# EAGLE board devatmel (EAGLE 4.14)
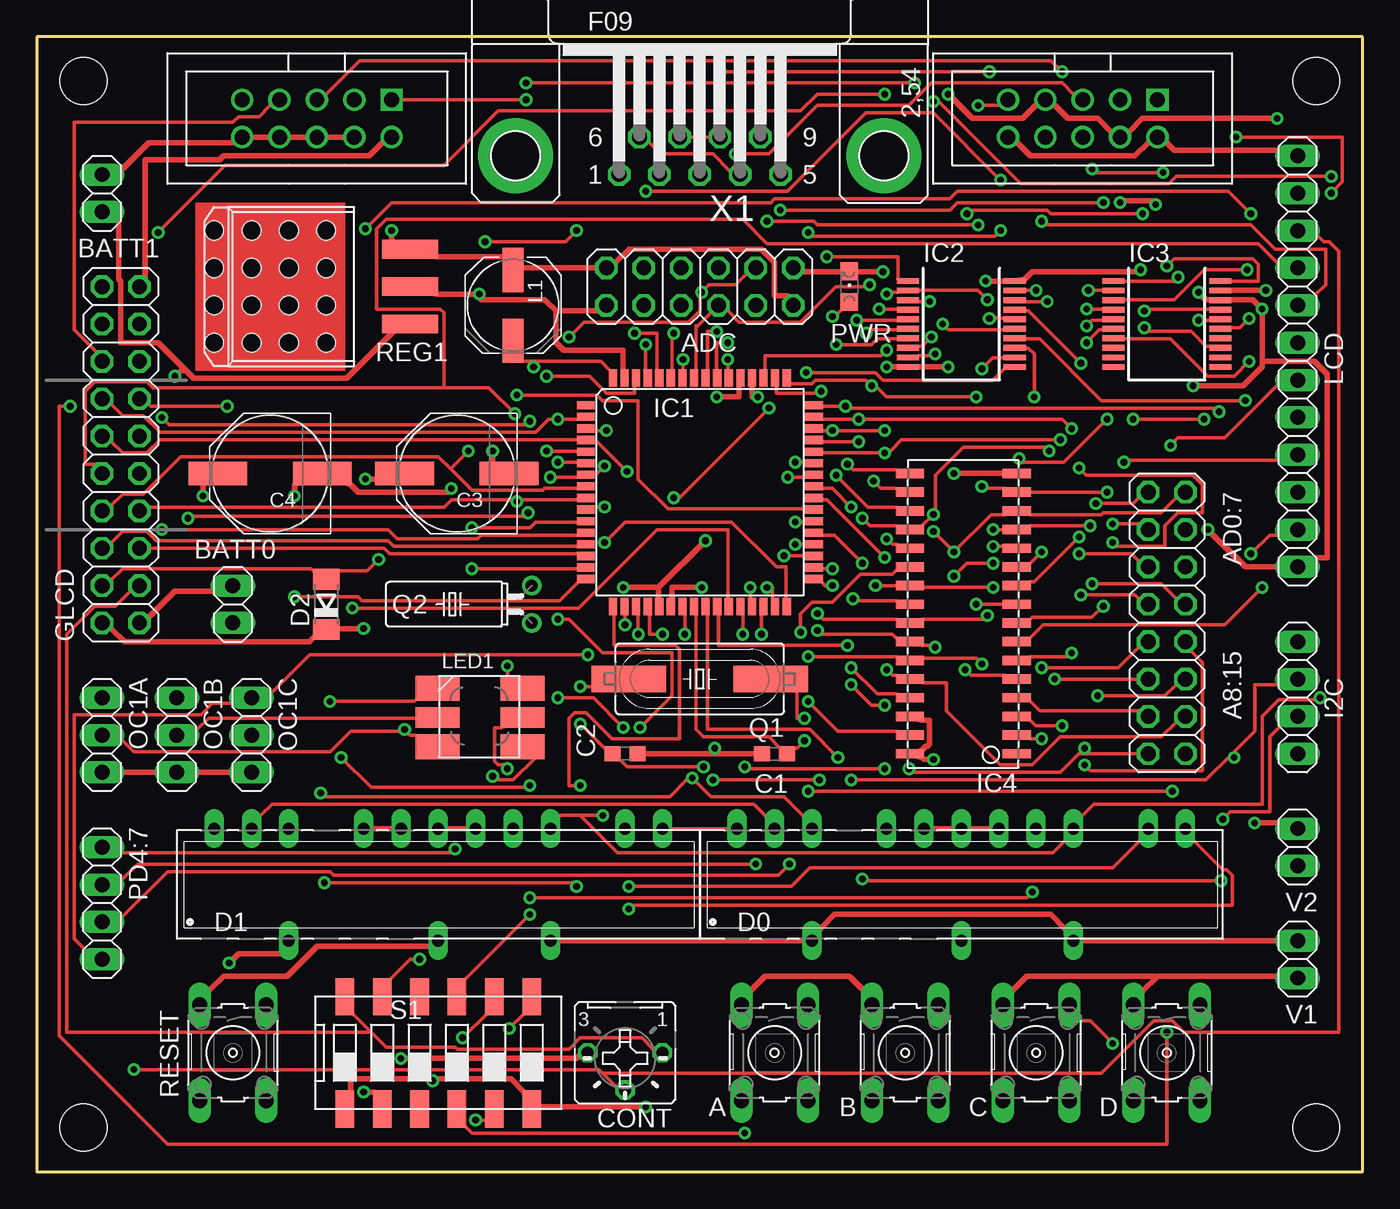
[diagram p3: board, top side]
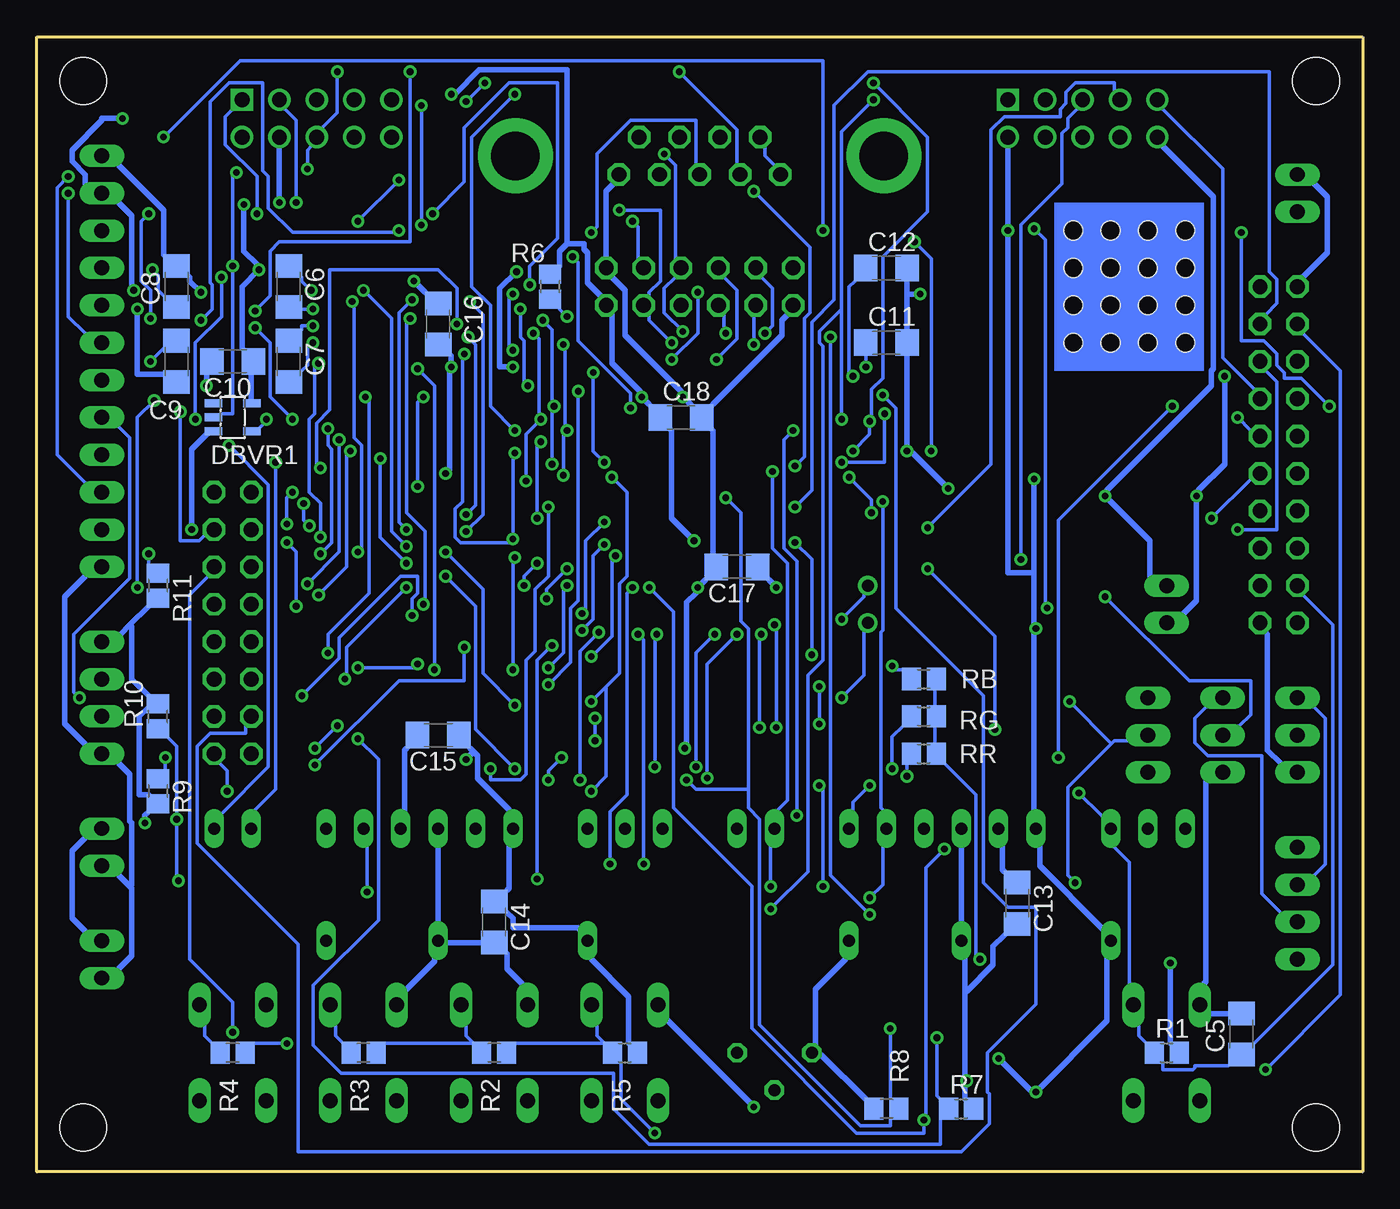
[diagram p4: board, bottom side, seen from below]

Size 90.15 x 77.14 mm. Coordinates in mm from the lower left corner, seen from the top.
Outline: 0,0 90.15,0 90.15,77.14 0,77.14 0,0
Copper layers (1*16): Top 0.035mm / dielectric 1.5mm / Bottom 0.035mm
Design rules "default": minimum track width 10mil, minimum drill 18mil, track to track 8mil, track to pad 8mil, pad to pad 8mil, via to via 8mil, smd to smd 8mil, copper to edge 40mil, drill to drill 8mil, minimum pad ring 10mil, minimum via ring 8mil, stop-mask expansion 4mil, vias tented up to drill 0mil, thermal gap 10mil
Net classes: 1 signal: width 0.254 mm; 2 power: width 0.381 mm
Holes 3.17 mm at 3.17,74.13 86.99,74.13 3.17,3.01 86.99,3.01

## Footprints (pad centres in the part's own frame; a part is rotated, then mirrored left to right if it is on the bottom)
B3F-10XX = drill 1.016 long: 1 -3.251,2.261; 2 3.251,2.261; 3 -3.251,-2.261; 4 3.251,-2.261
2X04 = drill 1.016 octagon: 1 -3.81,-1.27; 2 -3.81,1.27; 3 -1.27,-1.27; 4 -1.27,1.27; 5 1.27,-1.27; 6 1.27,1.27; 7 3.81,-1.27; 8 3.81,1.27
2X06 = drill 1.016 octagon: 1 -6.35,-1.27; 2 -6.35,1.27; 3 -3.81,-1.27; 4 -3.81,1.27; 5 -1.27,-1.27; 6 -1.27,1.27; 7 1.27,-1.27; 8 1.27,1.27; 9 3.81,-1.27; 10 3.81,1.27; 11 6.35,-1.27; 12 6.35,1.27
1X02 = drill 1.016 long: 1 -1.27,0; 2 1.27,0
C0603 = smd 1.1 x 1: 1 -0.85,0; 2 0.85,0
PANASONIC_F = smd 4 x 1.6: + 3.55,0; - -3.55,0
C1206 = smd 1.6 x 1.8: 1 -1.4,0; 2 1.4,0
B25P = drill 0.813 octagon: A -2.54,0; E 2.54,0; S 0,2.54
HCMS-291X = drill 0.813 long: 3 -10.16,-3.81; 7 0,-3.81; 10 7.62,-3.81; 14 15.24,3.81; 15 12.7,3.81; 17 7.62,3.81; 18 5.08,3.81; 19 2.54,3.81; 20 0,3.81; 21 -2.54,3.81; 22 -5.08,3.81; 24 -10.16,3.81; 25 -12.7,3.81; 26 -15.24,3.81
SOD80C = smd 1.4 x 1.8: A 1.7,0; C -1.7,0
SOT23-5L = smd 0.55 x 1.2: 1 -0.95,-1.3; 2 0,-1.3; 3 0.95,-1.3; 4 0.95,1.3; 5 -0.95,1.3
2X10 = drill 1.016 octagon: 1 -11.43,-1.27; 2 -11.43,1.27; 3 -8.89,-1.27; 4 -8.89,1.27; 5 -6.35,-1.27; 6 -6.35,1.27; 7 -3.81,-1.27; 8 -3.81,1.27; 9 -1.27,-1.27; 10 -1.27,1.27; 11 1.27,-1.27; 12 1.27,1.27; 13 3.81,-1.27; 14 3.81,1.27; 15 6.35,-1.27; 16 6.35,1.27; 17 8.89,-1.27; 18 8.89,1.27; 19 11.43,-1.27; 20 11.43,1.27
1X04 = drill 1.016 long: 1 -3.81,0; 2 -1.27,0; 3 1.27,0; 4 3.81,0
TQFP64 = smd 1.194 x 0.559: 1 -7.76,5.905; 2 -7.76,5.118; 3 -7.76,4.331; 4 -7.76,3.543; 5 -7.76,2.756; 6 -7.76,1.968; 7 -7.76,1.181; 8 -7.76,0.394; 9 -7.76,-0.394; 10 -7.76,-1.181; 11 -7.76,-1.968; 12 -7.76,-2.756; 13 -7.76,-3.543; 14 -7.76,-4.331; 15 -7.76,-5.118; 16 -7.76,-5.905; 33 7.76,-5.905; 34 7.76,-5.118; 35 7.76,-4.331; 36 7.76,-3.543; 37 7.76,-2.756; 38 7.76,-1.968; 39 7.76,-1.181; 40 7.76,-0.394; 41 7.76,0.394; 42 7.76,1.181; 43 7.76,1.968; 44 7.76,2.756; 45 7.76,3.543; 46 7.76,4.331; 47 7.76,5.118; 48 7.76,5.905 | smd 0.559 x 1.194: 17 -5.905,-7.76; 18 -5.118,-7.76; 19 -4.331,-7.76; 20 -3.543,-7.76; 21 -2.756,-7.76; 22 -1.968,-7.76; 23 -1.181,-7.76; 24 -0.394,-7.76; 25 0.394,-7.76; 26 1.181,-7.76; 27 1.968,-7.76; 28 2.756,-7.76; 29 3.543,-7.76; 30 4.331,-7.76; 31 5.118,-7.76; 32 5.905,-7.76; 49 5.905,7.76; 50 5.118,7.76; 51 4.331,7.76; 52 3.543,7.76; 53 2.756,7.76; 54 1.968,7.76; 55 1.181,7.76; 56 0.394,7.76; 57 -0.394,7.76; 58 -1.181,7.76; 59 -1.968,7.76; 60 -2.756,7.76; 61 -3.543,7.76; 62 -4.331,7.76; 63 -5.118,7.76; 64 -5.905,7.76
SSOP20 = smd 0.4 x 1.5: 1 -2.925,-3.625; 2 -2.275,-3.625; 3 -1.625,-3.625; 4 -0.975,-3.625; 5 -0.325,-3.625; 6 0.325,-3.625; 7 0.975,-3.625; 8 1.625,-3.625; 9 2.275,-3.625; 10 2.925,-3.625; 11 2.925,3.625; 12 2.275,3.625; 13 1.625,3.625; 14 0.975,3.625; 15 0.325,3.625; 16 -0.325,3.625; 17 -0.975,3.625; 18 -1.625,3.625; 19 -2.275,3.625; 20 -2.925,3.625
SOJ32/3 = smd 0.635 x 1.905: 1 -8.89,-3.759; 2 -7.62,-3.759; 3 -6.35,-3.759; 4 -5.08,-3.759; 5 -3.81,-3.759; 6 -2.54,-3.759; 7 -1.27,-3.759; 8 0,-3.759; 9 1.27,-3.759; 10 2.54,-3.759; 11 3.81,-3.759; 12 5.08,-3.759; 13 6.35,-3.759; 14 7.62,-3.759; 15 8.89,-3.759; 16 10.16,-3.759; 17 10.16,3.505; 18 8.89,3.505; 19 7.62,3.505; 20 6.35,3.505; 21 5.08,3.505; 22 3.81,3.505; 23 2.54,3.505; 24 1.27,3.505; 25 0,3.505; 26 -1.27,3.505; 27 -2.54,3.505; 28 -3.81,3.505; 29 -5.08,3.505; 30 -6.35,3.505; 31 -7.62,3.505; 32 -8.89,3.505
HDR10KEYED = drill 1.016 square: 1 -5.08,-1.27 | drill 1.016 round: 2 -5.08,1.27; 3 -2.54,-1.27; 4 -2.54,1.27; 5 0,-1.27; 6 0,1.27; 7 2.54,-1.27; 8 2.54,1.27; 9 5.08,-1.27; 10 5.08,1.27
PANASONIC_D = smd 3 x 1.4: 1 -2.4,0; 2 2.4,0
1X12 = drill 1.016 long: 1 -13.97,0; 2 -11.43,0; 3 -8.89,0; 4 -6.35,0; 5 -3.81,0; 6 -1.27,0; 7 1.27,0; 8 3.81,0; 9 6.35,0; 10 8.89,0; 11 11.43,0; 12 13.97,0
NSSM016A = smd 3 x 1.7: 1 -2.6,1.93; 3 -2.6,-2.07; 4 3.2,-2.07; 6 3.2,1.93 | smd 3 x 1.4: 2 -2.6,-0.07; 5 3.2,-0.07
1X03 = drill 1.016 long: 1 -2.54,0; 2 0,0; 3 2.54,0
CHIPLED_0805 = smd 1.2 x 1.2: A 0,-1.05; C 0,1.05
SM49 = smd 5.08 x 1.778: 1 -4.826,0; 2 4.826,0
TC38H = drill 0.813 round: 1 -1.27,0; 2 1.27,0
R0805 = smd 1.3 x 1.5: 1 -0.85,0; 2 0.85,0
DD-3DL = smd 1.27 x 3.81: P$1 -2.54,-5.715; P$2 0,-5.715; P$3 2.54,-5.715 | hole 1.27: -3.81,0; -1.27,0; 1.27,0; 3.81,0; 3.81,2.54; 1.27,2.54; -1.27,2.54; -3.81,2.54; -3.81,5.08; -1.27,5.08; 1.27,5.08; 3.81,5.08; 3.81,7.62; 1.27,7.62; -1.27,7.62; -3.81,7.62
219-6 = smd 1.27 x 2.54: 1 -6.35,-3.81; 2 -3.81,-3.81; 3 -1.27,-3.81; 4 1.27,-3.81; 5 3.81,-3.81; 6 6.35,-3.81; 7 6.35,3.81; 8 3.81,3.81; 9 1.27,3.81; 10 -1.27,3.81; 11 -3.81,3.81; 12 -6.35,3.81
F09HP = drill 1.016 octagon: 1 -5.486,-1.27; 2 -2.743,-1.27; 3 0,-1.27; 4 2.743,-1.27; 5 5.486,-1.27; 6 -4.115,1.27; 7 -1.372,1.27; 8 1.372,1.27; 9 4.115,1.27 | drill 3.302 pad 5.08 round: G1 -12.522,0; G2 12.522,0

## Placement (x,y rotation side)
A  [B3F-10XX]  50.16,8.09 270 top
A8:15  [2X04]  76.83,32.22 270 top
AD0:7  [2X04]  76.83,42.38 270 top
ADC  [2X06]  45.08,60.16 0 top
B  [B3F-10XX]  59.05,8.09 270 top
BATT0  [1X02]  13.33,38.57 90 top
BATT1  [1X02]  4.44,66.51 90 top
C  [B3F-10XX]  67.94,8.09 270 top
C1  22pF  [C0603]  50.16,28.41 180 top
C2  22pF  [C0603]  40,28.41 0 top
C3  470uF  [PANASONIC_F]  28.57,47.46 180 top
C4  220uF  [PANASONIC_F]  15.87,47.46 180 top
C5  10nF  [C1206]  8.25,9.36 90 bottom
C6  .47u  [C1206]  73.02,60.16 270 bottom
C7  .47u  [C1206]  73.02,55.08 270 bottom
C8  .47u  [C1206]  80.64,60.16 90 bottom
C9  .47u  [C1206]  80.64,55.08 90 bottom
C10  .1u  [C1206]  76.83,55.08 180 bottom
C11  .1u  [C1206]  32.38,56.35 0 bottom
C12  .1u  [C1206]  32.38,61.43 0 bottom
C13  .1u  [C1206]  23.49,18.25 270 bottom
C14  .1u  [C1206]  59.05,16.98 270 bottom
C15  .1u  [C1206]  62.86,29.68 180 bottom
C16  .1u  [C1206]  62.86,57.62 270 bottom
C17  .1u  [C1206]  42.54,41.11 180 bottom
C18  .1u  [C1206]  46.35,51.27 0 bottom
CONT  20k  [B25P]  40,8.09 180 top
D  [B3F-10XX]  76.83,8.09 270 top
D0  HCMS-291X  [HCMS-291X]  62.86,19.52 0 top
D1  HCMS-291X  [HCMS-291X]  27.3,19.52 0 top
D2  [SOD80C]  19.68,38.57 90 top
DBVR1  741G04  [SOT23-5L]  76.83,51.27 270 bottom
GLCD  [2X10]  5.71,48.73 270 top
I2C  [1X04]  85.72,32.22 270 top
IC1  MEGA128-A  [TQFP64]  45.08,46.19 0 top
IC2  74573DGV  [SSOP20]  62.86,57.62 270 top
IC3  MAX3223CAP  [SSOP20]  76.83,57.62 270 top
IC4  CY7C1009SOJ300  [SOJ32/3]  62.86,37.3 90 top
ISP  [HDR10KEYED]  19.04,71.59 180 top
JTAG  [HDR10KEYED]  71.11,71.59 180 top
L1  47u  [PANASONIC_D]  32.38,58.89 270 top
LCD  [1X12]  85.72,55.08 270 top
LED1  NSSM016A  [NSSM016A]  29.84,30.95 0 top
OC1A  [1X03]  4.44,29.68 270 top
OC1B  [1X03]  9.52,29.68 270 top
OC1C  [1X03]  14.6,29.68 270 top
PD4:7  [1X04]  4.44,18.25 270 top
PWR  [CHIPLED_0805]  55.24,60.16 0 top
Q1  [SM49]  45.08,33.49 180 top
Q2  32k768  [TC38H]  33.65,38.57 90 top
R1  4.7k  [R0805]  13.33,8.09 0 bottom
R2  3k33  [R0805]  59.05,8.09 180 bottom
R3  6k66  [R0805]  67.94,8.09 180 bottom
R4  23k3  [R0805]  76.83,8.09 180 bottom
R5  10k  [R0805]  50.16,8.09 0 bottom
R6  330  [R0805]  55.24,60.16 90 bottom
R7  10k  [R0805]  27.3,4.28 0 bottom
R8  10k  [R0805]  32.38,4.28 180 bottom
R9  4k7  [R0805]  81.91,25.87 270 bottom
R10  4k7  [R0805]  81.91,30.95 90 bottom
R11  4.7  [R0805]  81.91,39.84 270 bottom
RB  93  [R0805]  29.84,33.49 0 bottom
REG1  LM2940  [DD-3DL]  19.68,60.16 90 top
RESET  [B3F-10XX]  13.33,8.09 270 top
RG  100  [R0805]  29.84,30.95 0 bottom
RR  186  [R0805]  29.84,28.41 0 bottom
S1  219-6  [219-6]  27.3,8.09 0 top
V1  [1X02]  85.72,14.44 270 top
V2  [1X02]  85.72,22.06 270 top
X1  F  [F09HP]  45.08,69.05 0 top

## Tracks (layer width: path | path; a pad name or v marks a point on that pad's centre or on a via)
A0  (via drill 0.46)
  Top 0.254: v67.94,59.91 67.18,59.91 IC2.19 | v65.02,42.51 65.78,42.51 IC4.12
  Bottom 0.254: v67.94,59.91 66.03,58 66.03,43.52 v65.02,42.51
A1  (via drill 0.46)
  Top 0.254: v68.7,59.14 67.18,59.14 IC2.18 | v68.32,42.13 67.56,41.36 IC4.11
  Bottom 0.254: v68.7,59.14 68.57,59.02 68.57,49.87 68.07,49.37 68.07,42.38 v68.32,42.13
A2  (via drill 0.46)
  Top 0.254: v70.99,54.95 67.43,58.51 67.18,58.51 IC2.17 | v70.86,43.14 67.81,40.09 67.56,40.09 IC4.10
  Bottom 0.254: v70.99,54.95 71.24,54.7 71.24,51.52 71.62,51.14 71.62,46.19 70.86,45.43 v70.86,43.14
A3  (via drill 0.46)
  Top 0.254: v64.77,58 65.78,58 IC2.16 | v63.88,38.57 IC4.9
  Bottom 0.254: v64.77,58 65.02,57.75 65.02,44.79 63.75,43.52 63.75,38.7 v63.88,38.57
A4  (via drill 0.46)
  Top 0.254: v61.59,57.62 61.97,57.24 65.78,57.24 IC2.15 | v70.86,47.84 71.37,47.33 78.61,47.33 79.24,46.7 79.24,44.79 77.59,44.79 76.7,43.9 76.7,42.51 73.4,42.51 v73.15,42.76 | v72.51,38.44 71.75,37.68 67.69,37.68 67.56,37.55 IC4.8
  Bottom 0.254: v61.59,57.62 61.59,60.03 62.86,61.3 70.23,61.3 70.23,51.78 71.11,50.89 71.11,48.09 v70.86,47.84 | v73.15,42.76 72.51,42.13 v72.51,38.44
A5  (via drill 0.46)
  Top 0.254: v82.16,52.41 72.38,52.41 68.19,56.6 67.18,56.6 IC2.14 | v83.31,39.71 80.77,37.17 68.45,37.17 67.56,36.28 IC4.7
  Bottom 0.254: v82.16,52.41 83.31,51.27 v83.31,39.71
A6  (via drill 0.46)
  Top 0.254: v67.81,52.67 67.81,55.59 67.43,55.97 67.18,55.97 IC2.13 | v70.35,35.27 70.1,35.01 67.56,35.01 IC4.6
  Bottom 0.254: v67.81,52.67 67.56,52.41 67.56,39.33 70.35,36.54 v70.35,35.27
A7  (via drill 0.46)
  Top 0.254: v64.26,54.57 65.02,55.33 65.78,55.33 IC2.12 | v63.11,34.12 63.5,33.74 65.78,33.74 IC4.5
  Bottom 0.254: v64.26,54.57 63.11,53.43 v63.11,34.12
ADC0  (via drill 0.46)
  Top 0.254: v41.4,56.22 41.4,54.45 IC1.61
  Bottom 0.254: v41.4,56.22 41.4,58.25 ADC.3
ADC1  (via drill 0.46)
  Top 0.254: v40.64,56.98 42.16,56.98 42.16,54.45 IC1.60
  Bottom 0.254: v40.64,56.98 40.13,57.49 40.13,60.03 40.89,60.8 ADC.4
ADC2  (via drill 0.46)
  Top 0.254: v43.3,56.98 43.18,56.98 43.18,54.45 IC1.59
  Bottom 0.254: v43.3,56.98 43.43,57.11 43.43,58.25 ADC.5
ADC3  (via drill 0.46)
  Top 0.254: v43.94,55.21 43.94,54.45 IC1.58
  Bottom 0.254: v43.94,55.21 42.54,56.6 42.54,59.91 43.43,60.8 ADC.6
AREF  (via drill 0.46)
  Top 0.254: v34.67,54.06 37.59,54.06 38.73,52.92 40.64,52.92 40.64,53.43 IC1.62
  Bottom 0.254: v34.67,54.06 34.92,54.32 34.92,60.16 34.54,60.54 C12.1
AVCC  (via drill 0.46)
  Top 0.254: 33.78,55.08 33.02,55.08 L1.2 | 33.78,55.08 38.35,55.08 38.98,54.45 IC1.64 | 33.78,55.08 v33.78,54.7
  Bottom 0.254: v33.78,54.7 33.78,55.46 C11.1
BANK  (via drill 0.46)
  Top 0.254: v28.95,9.11 30.6,10.76 S1.8 | v68.32,29.43 67.56,29.43 IC4.2
  Bottom 0.254: v28.95,9.11 28.95,5.17 28.7,4.92 R7.1 28.7,3.64 28.7,1.87 48.51,1.87 50.92,4.28 50.92,6.69 69.46,6.69 71.37,8.6 71.37,12.66 66.92,17.11 66.92,28.03 v68.32,29.43
BATT  (via drill 0.46)
  Top 0.381: v11.3,45.94 11.3,46.7 C4.+ | 10.03,54.57 10.66,53.94 21.08,53.94 24.25,57.11 REG1.P$1 | 10.03,54.57 8.25,56.35 5.71,56.35 5.71,60.54 5.58,60.67 5.58,64.61 BATT1.1 | v9.39,54.06 9.77,54.45 9.9,54.45 10.03,54.57
  Bottom 0.381: BATT0.1 12.19,37.94 11.3,38.82 v11.3,45.94 11.17,46.32 9.39,48.09 v9.39,54.06
BL+  (via drill 0.46)
  Top 0.254: v82.55,42 83.81,43.27 84.32,43.27 LCD.11
  Bottom 0.254: v82.55,42 82.55,41.24 R11.1
CONT  (via drill 0.46)
  Top 0.254: 38.54,6.63 38.22,6.95 v6.6,6.95 | 38.54,6.63 39.37,5.8 CONT.S | LCD.3 87.12,63.59 87.5,63.21 87.88,63.21 88.51,62.57 88.51,9.49 77.97,9.49 77.21,10.25 75.94,10.25 72.38,6.69 38.6,6.69 38.54,6.63
  Bottom 0.254: v6.6,6.95 1.52,12.03 1.52,54.45 4.06,56.98 GLCD.3
EXTM_EN  (via drill 0.46)
  Top 0.254: v32.13,9.74 33.14,10.76 S1.7 | v53.72,62.19 58.54,62.19 58.54,60.67 IC2.1 | v49.78,51.91 43.68,45.81 v43.3,45.81 | v51.94,36.66 51.94,37.94 52.7,38.7 54.1,38.7 56,40.6 58.16,40.6 58.41,40.86 IC4.22 | v45.97,26.63 v53.21,26.63
  Bottom 0.254: v32.13,9.74 32.13,4.92 R8.1 32.13,3.64 32.13,3.14 34.16,3.14 41.02,10 41.02,23.96 41.78,24.73 41.78,26 | v53.72,62.19 53.34,61.81 53.34,56.48 49.78,52.92 v49.78,51.91 | v43.3,45.81 42.29,44.79 42.29,37.43 41.78,36.92 41.78,26 | v51.94,36.66 53.21,35.39 v53.21,26.63 | v45.97,26.63 45.33,26 41.78,26
GCS1
  Top 0.254: IC1.13 36.83,42.51 24.25,42.51 23.87,42.89 8.12,42.89 7.49,43.52 5.84,43.52 5.08,42.76 GLCD.15
GCS2
  Top 0.254: IC1.14 36.83,42 24,42 23.62,42.38 GLCD.16
GDI  (via drill 0.46)
  Top 0.254: v38.6,45.17 37.84,45.17 IC1.10
  Bottom 0.254: v38.6,45.17 37.46,46.32 37.46,57.75 35.94,59.27 35.94,72.48 33.65,74.77 6.34,74.77 6.34,61.18 5.84,60.67 5.84,59.02 6.6,58.25 GLCD.4
GE  (via drill 0.46)
  Top 0.254: v8.5,43.65 23.87,43.65 24.51,43.02 29.97,43.02 30.22,43.27 36.83,43.27 IC1.12
  Bottom 0.254: v8.5,43.65 5.84,43.65 5.84,53.68 6.6,54.45 GLCD.6
GND  (via drill 0.46)
  Top 0.381: JTAG.10 66.67,69.94 67.56,69.05 74.67,69.05 75.56,69.94 JTAG.2 76.83,69.94 77.34,69.43 84.32,69.43 LCD.1 | v78.99,59.78 79.5,59.27 79.75,59.27 IC3.18 81.15,59.27 82.67,59.27 v83.31,58.64 83.31,55.08 | v78.61,53.43 82.04,53.43 83.31,54.7 83.31,55.08 | D0.21 D0.20 D0.19 | A.3 48.64,12.41 49.53,13.3 55.24,13.3 56.13,12.41 B.3 | v79.62,43.65 82.16,41.11 LCD.12 86.86,41.74 87.75,41.74 87.75,54.19 86.86,55.08 83.31,55.08 | 76.07,13.17 76.19,13.3 84.32,13.3 V1.2 | 76.07,13.17 75.31,12.41 D.3 | C.3 66.42,12.41 67.3,13.3 75.94,13.3 76.07,13.17 | 35.3,58.51 35.3,56.35 35.81,55.84 39.87,55.84 39.87,54.45 IC1.63 | 35.3,58.51 38.1,58.51 ADC.1 | REG1.P$2 27.17,59.65 v30.09,59.65 30.22,59.27 34.54,59.27 35.3,58.51 | v30.98,48.98 30.98,48.22 C3.- | v61.97,54.7 59.94,54.7 IC2.10 58.54,54.7 v57.78,54.7 | v62.35,47.46 IC4.16 | ADC.12 52.07,61.18 54.73,61.18 PWR.C 55.75,61.18 v57.53,61.18 | 46.1,28.41 C2.2 | 46.1,28.41 C1.2 | v45.21,39.71 43.18,39.71 43.18,38.95 IC1.22 | v46.22,52.67 47.75,52.67 47.75,53.43 IC1.53 | v46.1,28.79 46.1,28.41 | 26.92,6.31 32.25,6.31 33.14,5.42 S1.6 34.16,4.41 v41.4,4.41 | 26.92,6.31 21.33,6.31 21.33,5.42 S1.1 | D1.20 D1.19 | v26.92,6.18 26.92,6.31 | ISP.4 ISP.6 ISP.8 ISP.10 13.33,69.94 7.62,69.94 5.84,68.16 BATT1.2 | GLCD.20 7.62,37.68 9.39,39.46 11.93,39.46 BATT0.2 | v17.52,45.94 17.52,46.7 C4.- 21.33,46.7 21.84,46.19 27.93,46.19 v28.19,46.44 | OC1A.3 OC1B.3 OC1C.3 | D1.7 26.66,15.33 19.04,15.33 17.01,13.3 12.7,13.3 11.81,12.41 RESET.3
  Bottom 0.381: v78.99,59.78 79.75,60.54 79.75,60.8 C8.2 81.53,62.32 81.53,65.37 84.58,68.41 LCD.1 | v83.31,58.64 83.31,54.19 81.53,54.19 C9.1 | v78.61,53.43 78.61,54.19 C10.2 | C15.2 65.02,28.79 65.15,28.66 65.15,24.6 D0.19 | D0.7 62.23,15.58 59.94,15.58 C14.2 58.16,14.82 58.16,13.81 57.15,12.79 B.3 | C.3 65.02,12.41 63.11,14.31 63.11,14.44 D0.7 | D0.7 D0.20 | v79.62,43.65 79.62,49.11 78.61,50.13 DBVR1.3 | 83.81,19.39 83.69,19.27 83.69,14.69 84.58,13.81 V1.2 | 83.81,19.39 84.58,20.15 V2.2 | 83.81,19.39 83.69,19.52 83.69,23.71 83.81,23.84 83.81,27.01 84.58,27.77 I2C.4 86.86,29.04 88.26,30.44 88.26,39.08 86.86,40.48 LCD.12 | 30.98,59.65 30.98,60.54 C12.2 | 30.98,59.65 30.98,57.24 C11.2 30.98,55.46 v30.98,48.98 30.6,48.86 v28.19,46.44 | 30.98,59.65 v30.09,59.65 | C16.2 61.97,55.46 v61.97,54.7 62.1,54.32 62.1,47.71 v62.35,47.46 | X1.5 50.92,67.14 51.43,66.64 ADC.12 51.05,60.8 50.16,59.91 50.16,56.86 46.35,53.05 v46.22,52.67 45.72,52.16 C18.2 | C18.2 44.19,50.38 44.19,42 C17.2 44.7,40.22 v45.21,39.71 45.33,39.33 45.97,38.7 45.97,28.92 v46.1,28.79 | v57.78,54.7 58.67,54.7 58.67,60.03 v57.53,61.18 | ADC.1 39.11,58.25 39.49,57.87 39.49,56.86 44.19,52.16 C18.2 | 27.05,12.28 27.05,14.44 D1.7 D1.20 | 27.05,12.28 27.05,6.18 | 27.05,6.18 27.05,4.92 R7.2 | C13.2 24.38,16.09 25.14,15.33 25.14,14.06 26.92,12.28 27.05,12.28 | 27.05,6.18 v26.92,6.18 | GLCD.1 4.06,60.8 2.41,62.45 2.41,66.26 3.3,67.14 BATT1.2 | BATT0.2 14.47,40.48 14.47,42.89 v17.52,45.94 17.39,46.32 10.28,53.43 10.28,54.45 10.16,54.57 10.16,66.26 13.58,69.69 ISP.10 | C5.2 9.14,10.76 10.41,10.76 RESET.3 10.79,12.79 10.66,12.92 10.66,26.5 OC1B.3
  Bottom 0.381: GLCD.20 6.6,36.66 6.47,36.54 6.47,28.66 5.58,27.77 OC1A.3 | v41.4,4.41 47.24,10.25 A.3
GRW  (via drill 0.46)
  Top 0.254: v29.59,43.78 33.52,43.78 33.9,44.16 36.83,44.16 IC1.11 | GLCD.5 4.06,55.71 2.54,57.24 2.54,71.34 13.33,71.34 13.71,71.72 15.11,71.72 15.87,72.48 ISP.7
  Bottom 0.254: v29.59,43.78 25.27,48.09 25.27,70.83 24.38,71.72 20.57,71.72 20.57,72.22 20.19,72.61 20.19,73.37 19.55,74 16.89,74 16.89,73.5 ISP.7
KEYS  (via drill 0.46)
  Top 0.254: v48.13,2.63 29.59,2.63 29.08,3.14 S1.4
  Bottom 0.254: 51.62,8.79 52.07,9.23 52.07,9.87 A.1 | 51.62,8.79 51.56,8.73 R5.1 50.41,7.46 50.41,4.92 v48.13,2.63 | R2.1 57.65,8.73 51.68,8.73 51.62,8.79
N$1  (via drill 0.46)
  Top 0.254: v71.5,59.91 72.51,59.91 IC3.2
  Bottom 0.254: v71.5,59.91 72.13,60.54 72.13,60.8 C6.1
N$2  (via drill 0.46)
  Top 0.254: v71.37,58.64 72.51,58.64 IC3.4
  Bottom 0.254: v71.37,58.64 72.13,58.64 C6.2
N$3  (via drill 0.46)
  Top 0.254: v54.1,58.13 54.22,58.13 54.73,58.64 PWR.A
  Bottom 0.254: v54.1,58.13 54.61,58.64 54.61,58.76 R6.1
N$4
  Bottom 0.254: 60.51,8.79 60.96,9.23 60.96,9.87 B.1 | 60.51,8.79 60.45,8.73 R2.2 | R3.1 66.54,8.73 60.57,8.73 60.51,8.79
N$5  (via drill 0.46)
  Top 0.254: v73.15,8.73 71.62,10.25 70.86,10.25 C.1
  Bottom 0.254: R3.2 69.34,8.73 69.84,9.23 69.84,9.87 C.1 | v73.15,8.73 75.43,8.73 R4.1
N$6  (via drill 0.46)
  Top 0.254: v71.37,57.49 71.75,57.87 72.51,57.87 IC3.5
  Bottom 0.254: v71.37,57.49 72.13,57.49 72.13,57.24 C7.1
N$7  (via drill 0.46)
  Top 0.254: v71.37,56.35 72.26,57.24 72.51,57.24 IC3.6
  Bottom 0.254: v71.37,56.35 71.75,55.97 71.75,54.83 72.13,54.45 C7.2
N$8
  Bottom 0.254: R4.2 78.23,8.73 78.73,9.23 78.73,9.87 D.1
N$15  (via drill 0.46)
  Top 0.254: v82.29,61.3 79.37,61.3 77.34,59.27 73.91,59.27 IC3.3
  Bottom 0.254: v82.29,61.3 81.91,60.92 81.91,59.91 81.53,59.52 C8.1
N$16  (via drill 0.46)
  Top 0.254: v82.42,55.08 81.4,54.06 79.62,54.06 77.08,56.6 73.91,56.6 IC3.7
  Bottom 0.254: v82.42,55.08 81.53,55.97 C9.2
N$22  (via drill 0.46)
  Top 0.254: v30.98,26.89 31.24,26.63 32.38,26.63 33.9,28.16 LED1.4
  Bottom 0.254: v30.98,26.89 30.98,27.77 RR.1
N$23  (via drill 0.46)
  Top 0.254: v32,27.39 31.74,27.65 31.36,27.65 31.11,27.9 31.11,30.19 31.62,30.19 LED1.5
  Bottom 0.254: v32,27.39 32,29.55 31.24,30.31 RG.1
N$24  (via drill 0.46)
  Top 0.254: v32,34.38 32,33.62 LED1.6
  Bottom 0.254: v32,34.38 32,34.12 31.24,34.12 RB.1
N$26
  Top 0.254: D1.14 D0.26
N$28
  Top 0.254: D1.25 15.24,24.22 16,24.98 48.76,24.98 49.53,24.22 D0.25
N$49
  Top 0.254: X1.7 X1.8
N$50
  Top 0.254: X1.4 47.11,68.03 45.97,69.18 42.41,69.18 41.65,69.94 X1.6
  Bottom 0.254: X1.1 40,68.41 40.64,69.05 40.64,69.69 X1.6
OC1A  (via drill 0.46)
  Top 0.254: v29.59,40.98 36.83,40.98 IC1.15 | LED1.3 25.78,29.68 25.39,29.68 v25.01,30.06 24.63,29.93 21.33,29.93 19.93,28.54 6.6,28.54 5.84,29.3 OC1A.2
  Bottom 0.254: v29.59,40.98 25.01,36.41 v25.01,30.06
OC1B  (via drill 0.46)
  Top 0.254: v17.52,39.08 21.84,39.08 22.09,38.82 35.55,38.82 36.83,40.09 IC1.16 | LED1.2 25.78,30.82 11.68,30.82 10.92,30.06 OC1B.2
  Bottom 0.254: v17.52,39.08 11.81,33.36 7.62,33.36 7.62,31.08 8.38,30.31 OC1B.2
OC1C  (via drill 0.46)
  Top 0.254: v36.95,26.25 36.19,26.25 36.19,30.82 36.57,31.2 37.33,31.2 39.11,29.43 43.68,29.43 43.68,35.52 43.43,35.78 39.24,35.78 39.24,37.94 IC1.17 | v36.7,19.39 36.44,19.65 v19.55,19.65 | v19.93,31.97 25.65,31.97 25.78,32.09 LED1.1
  Bottom 0.254: v36.95,26.25 36.7,26 v36.7,19.39 | v19.55,19.65 20.06,20.15 20.06,26.12 17.08,29.11 | 17.08,29.11 16.89,29.3 16,29.3 OC1C.2 | 17.08,29.11 v19.93,31.97
PA0  (via drill 0.46)
  Top 0.254: v71.62,43.9 67.56,43.9 IC4.13 v65.02,43.65 | v72,45.43 74.54,45.43 74.92,45.81 AD0:7.1 | v57.78,55.84 57.4,55.46 49.53,55.46 49.53,54.45 IC1.51 | v57.78,59.65 57.91,59.78 58.54,59.78 IC2.2 59.94,59.91 64,59.91 v64.64,59.27
  Bottom 0.254: v71.62,43.9 72,44.28 v72,45.43 | v57.78,55.84 58.03,56.1 58.03,59.4 v57.78,59.65 | v65.02,43.65 65.53,44.16 65.53,58.38 v64.64,59.27
PA1  (via drill 0.46)
  Top 0.254: v53.34,53.05 53.21,52.92 50.29,52.92 50.29,53.43 IC1.50 | v55.37,33.11 56.76,31.71 v57.65,31.71 | v60.7,59.14 59.94,59.14 IC2.3 | v60.96,43.52 v62.35,42.13 64.89,44.67 65.78,44.67 IC4.14 67.56,44.67 72.38,44.67 72.51,44.79 76.45,44.79 77.46,45.81 AD0:7.2
  Bottom 0.254: v53.34,53.05 53.34,38.82 53.84,38.32 53.84,34.63 v55.37,33.11 | v57.65,31.71 59.81,33.87 59.81,39.59 v62.35,42.13 | v60.7,59.14 59.81,58.25 59.81,44.67 v60.96,43.52
PA2  (via drill 0.46)
  Top 0.254: v57.27,58.64 58.54,58.64 IC2.4 | IC1.49 51.18,53.56 52.7,53.56 52.95,53.81 56.38,53.81 v56.76,53.43 57.15,53.3 57.78,52.67 v63.88,52.67 | v73.15,44.03 74.92,44.03 AD0:7.3 | v72.77,46.19 IC4.15 65.78,46.44 64.38,46.44 v64.26,46.57
  Bottom 0.254: v56.76,53.43 57.02,53.68 57.02,56.48 57.27,56.73 v57.27,58.64 | v72.77,46.19 73.15,45.81 v73.15,44.03 | v63.88,52.67 64.26,52.29 v64.26,46.57
PA3  (via drill 0.46)
  Top 0.254: v55.11,48.09 55.49,47.71 58.41,47.71 IC4.17 | IC1.48 53.34,52.03 v54.99,52.03 55.37,51.91 80.13,51.91 v80.39,51.65 | v55.75,57.87 58.54,57.87 IC2.5
  Bottom 0.254: v55.11,48.09 55.11,51.91 v54.99,52.03 55.11,52.41 55.11,57.24 v55.75,57.87 | v80.39,51.65 80.39,42.89 79.12,42.89 78.73,43.27 AD0:7.4
PA4  (via drill 0.46)
  Top 0.254: v56.89,46.95 57.4,46.44 58.41,46.44 IC4.18 | IC1.47 53.34,51.14 v55.88,51.14 69.72,51.14 v70.35,50.51 | v56.38,56.98 56.64,57.24 58.54,57.24 IC2.6 | v70.86,42 74.42,42 74.92,41.49 AD0:7.5
  Bottom 0.254: v56.89,46.95 56.89,50.13 v55.88,51.14 56,51.52 56,56.6 v56.38,56.98 | v70.86,42 70.1,42.76 70.1,49.11 70.35,49.37 v70.35,50.51
PA5  (via drill 0.46)
  Top 0.254: v54.35,47.33 56.51,45.17 58.41,45.17 IC4.19 | IC1.46 53.34,50.38 v54.1,50.38 v57.65,50.38 | v54.35,56.22 56.76,56.22 57.15,56.6 58.54,56.6 IC2.7 | v76.83,9.49 76.83,1.87 8.89,1.87 1.52,9.23 1.52,52.03 v2.28,52.03 | v8.25,63.84 12.82,68.41 27.68,68.41 31.36,72.1 51.94,72.1 53.08,73.24 v57.65,73.24
  Bottom 0.254: v54.35,47.33 54.35,50.13 v54.1,50.38 54.22,50.76 54.22,56.1 v54.35,56.22 | v76.83,9.49 76.83,11.52 79.75,14.44 79.75,39.2 78.48,40.48 AD0:7.6 | v2.28,52.03 4.19,53.94 5.33,53.94 5.33,54.32 5.84,54.83 5.84,55.59 6.73,56.48 8.25,56.48 v8.25,63.84 | v57.65,73.24 60.57,70.32 60.57,60.16 59.3,58.89 59.3,52.03 v57.65,50.38
PA6  (via drill 0.46)
  Top 0.254: v55.88,49.62 53.34,49.62 IC1.45 | v56.13,44.41 56.64,43.9 58.41,43.9 IC4.20 60.19,43.9 v60.96,44.67 61.08,45.05 61.08,47.33 62.99,49.24 68.57,49.24 v68.83,48.98 | v60.83,56.73 60.19,56.1 59.94,56.1 IC2.8 | v70.99,39.2 74.67,39.2 74.92,38.95 AD0:7.7
  Bottom 0.254: v55.88,49.62 56.13,49.37 v56.13,44.41 | v60.83,56.73 60.32,56.22 60.32,45.3 v60.96,44.67 | v70.99,39.2 69.08,41.11 69.08,48.73 v68.83,48.98
PA7  (via drill 0.46)
  Top 0.254: v57.78,43.02 58.16,42.63 58.41,42.63 IC4.21 | IC1.44 53.34,48.86 v57.65,48.86 58.03,48.98 58.8,49.75 v69.59,49.75 | v61.08,55.59 60.96,55.46 59.94,55.46 IC2.9 | v71.75,39.97 76.45,39.97 77.46,38.95 AD0:7.8
  Bottom 0.254: v57.65,48.86 57.78,48.73 v57.78,43.02 58.03,42.76 61.34,42.76 61.72,43.14 61.72,45.05 61.21,45.55 61.21,55.46 v61.08,55.59 | v71.75,39.97 69.59,42.13 v69.59,49.75
PC0  (via drill 0.46)
  Top 0.254: v50.8,41.87 52.32,41.87 IC1.35 | v52.45,35.01 58.41,35.01 IC4.27 60.19,34.89 63.88,34.89 v64.26,34.51 | v68.32,34.25 73.53,34.25 74.92,35.65 A8:15.1
  Bottom 0.254: v50.8,41.87 51.05,41.62 51.05,36.41 v52.45,35.01 | v68.32,34.25 64.26,34.25 v64.26,34.51
PC1  (via drill 0.46)
  Top 0.254: v51.56,42.63 52.32,42.63 IC1.36 | v53.08,36.79 53.34,36.54 58.16,36.54 58.41,36.28 IC4.26 60.19,35.78 60.96,35.78 v61.08,35.65 | v71.24,27.65 71.62,27.27 79.24,27.27 79.24,34.63 78.48,35.39 A8:15.2
  Bottom 0.254: v51.56,42.63 52.32,41.87 52.32,37.55 v53.08,36.79 | v71.24,27.65 65.53,33.36 61.08,33.36 v61.08,35.65
PC2  (via drill 0.46)
  Top 0.254: v56.13,41.36 54.22,43.27 53.34,43.27 IC1.37 | v57.02,39.84 IC4.23 60.19,39.71 v65.02,39.71 | v69.21,33.49 A8:15.3
  Bottom 0.254: v56.13,41.36 57.02,40.48 v57.02,39.84 | v69.21,33.49 69.08,33.62 69.08,35.65 v65.02,39.71
PC3  (via drill 0.46)
  Top 0.254: v51.56,44.16 52.32,44.16 IC1.38 | v53.08,37.94 53.46,37.55 58.41,37.55 IC4.25 60.19,37.55 64.38,37.55 v64.64,37.81 | v72.13,32.35 76.7,32.35 77.46,33.11 A8:15.4
  Bottom 0.254: v51.56,44.16 52.83,42.89 52.83,38.19 v53.08,37.94 | v72.13,32.35 69.59,34.89 69.59,36.28 65.4,40.48 64.26,40.48 64.26,39.33 64.64,38.95 v64.64,37.81
PC4  (via drill 0.46)
  Top 0.254: v32.63,52.79 38.1,52.79 38.48,52.41 40.89,52.41 40.89,47.08 42.92,45.05 52.32,45.05 IC1.39 | IC4.4 67.56,31.97 68.19,31.33 74.92,31.33 A8:15.5
  Bottom 0.254: v32.63,52.79 31.74,51.91 31.74,38.32 25.78,32.35 25.78,19.65 24.12,18 22.22,18 22.22,11.39 25.52,8.09 25.52,5.42 25.39,5.3 25.39,3.26 27.3,1.36 72.38,1.36 72.38,15.46 79.24,22.31 79.24,28.92 78.35,29.81 75.94,29.81 75.94,30.31 A8:15.5
PC5  (via drill 0.46)
  Top 0.254: v57.65,41.74 53.72,45.68 53.34,45.68 IC1.40 | v57.78,34.12 58.16,33.74 58.41,33.74 IC4.28 60.19,33.24 61.84,33.24 61.84,31.33 65.53,27.65 67.69,27.65 69.59,29.55 76.45,29.55 77.46,30.57 A8:15.6
  Bottom 0.254: v57.65,41.74 57.78,41.62 v57.78,34.12
PC6  (via drill 0.46)
  Top 0.254: v55.37,45.17 54.1,46.44 53.34,46.44 IC1.41 | v59.3,27.39 59.56,27.14 69.59,27.14 70.86,28.41 71.24,28.41 | 71.24,28.41 A8:15.7 | v69.72,30.31 67.94,30.31 67.56,30.7 IC4.3 | 71.24,28.41 v71.24,28.79
  Bottom 0.254: v55.37,45.17 55.37,40.48 56.26,39.59 56.26,35.39 56.89,34.76 56.89,27.01 57.27,26.63 59.3,26.63 v59.3,27.39 | v71.24,28.79 v69.72,30.31
PC7  (via drill 0.46)
  Top 0.254: v51.05,47.21 52.32,47.21 IC1.42 | v52.45,31.97 54.48,29.93 58.41,29.93 IC4.31 | v52.45,25.87 v77.21,25.87
  Bottom 0.254: v51.05,47.21 50.03,46.19 50.03,40.48 50.54,39.97 50.54,33.87 51.49,32.92 | 51.49,32.92 v52.45,31.97 | v77.21,25.87 77.21,27.27 77.72,27.77 A8:15.8 | v52.45,25.87 51.43,26.89 51.43,32.85 51.49,32.92
PD4  (via drill 0.46)
  Top 0.254: v48.51,39.71 48.51,38.95 IC1.29 | v29.84,3.52 30.6,3.52 S1.5 | v28.44,21.93 28.19,21.68 5.84,21.68 PD4:7.1
  Bottom 0.254: v48.51,39.71 46.86,38.06 46.86,24.73 41.52,19.39 41.52,9.74 34.41,2.63 29.84,2.63 v29.84,3.52 29.71,3.9 29.71,20.66 v28.44,21.93
PD5  (via drill 0.46)
  Top 0.254: v49.27,36.54 49.27,37.94 IC1.30 | v48.89,20.92 6.85,20.92 5.84,19.9 PD4:7.2
  Bottom 0.254: v49.27,36.54 48.89,36.16 v48.89,20.92 | OC1A.1 3.3,31.58 2.54,30.82 2.54,20.92 3.3,20.15 PD4:7.2
PD6  (via drill 0.46)
  Top 0.254: v49.65,39.71 50.03,39.71 50.03,38.95 IC1.31 | v51.18,20.92 50.41,20.15 20.19,20.15 19.93,20.41 8.89,20.41 5.84,17.36 PD4:7.3
  Bottom 0.254: v49.65,39.71 50.03,39.33 50.03,25.62 51.18,24.47 v51.18,20.92 | OC1B.1 10.66,31.58 11.43,30.82 11.43,29.17 10.54,28.28 6.85,28.28 6.85,18.88 5.58,17.61 PD4:7.3
PD7  (via drill 0.46)
  Top 0.254: v38.6,42.76 40,44.16 47.24,44.16 50.29,41.11 50.92,41.11 50.92,38.95 IC1.32 | v37.46,35.14 18.54,35.14 16,32.6 OC1C.1 13.2,31.84 11.93,31.84 11.17,31.08 2.54,31.08 2.54,15.84 3.3,15.08 PD4:7.4
  Bottom 0.254: v38.6,42.76 37.46,41.62 v37.46,35.14
PE0  (via drill 0.46)
  Top 0.254: v77.08,49.37 77.59,49.87 80.77,49.87 84.32,53.43 LCD.7 | IC1.2 36.83,51.14 v35.43,51.14 34.79,51.14 33.9,50.25 8.38,50.25 7.23,51.4 5.84,51.4 5.08,52.16 GLCD.7 | v33.27,72.86 ISP.1 | v40.25,17.87 40.51,18.12 81.27,18.12 81.27,20.15 80.89,20.54 80.64,20.54 78.73,22.44 D0.14
  Bottom 0.254: v77.08,49.37 74.42,46.7 74.42,27.52 77.59,24.35 D0.14 | v33.27,72.86 35.43,70.7 35.43,58.64 | v35.43,51.14 35.43,58.64 | v40.25,17.87 37.71,20.41 37.71,33.74 36.7,34.76 36.7,56.1 36.95,56.35 36.95,57.11 35.43,58.64
PE1  (via drill 0.46)
  Top 0.254: v38.73,50.38 37.84,50.38 IC1.3 | 36.95,24.22 35.55,24.22 D1.17 | 36.95,24.22 v38.48,24.22 | 36.95,24.22 39.49,21.68 69.08,21.68 69.84,22.44 D0.17 71.11,24.22 71.88,24.98 83.31,24.98 83.31,30.95 84.45,32.09 87.12,32.09 v87.24,32.22 | v12.95,52.03 7.74,52.03 7.62,52.16 GLCD.8 | v20.7,28.16 22.73,26.12 33.4,26.12 v33.52,26.25
  Bottom 0.254: GLCD.8 7.36,53.17 9.52,55.33 9.52,68.16 13.58,72.22 ISP.9 | v38.73,50.38 39.37,49.75 39.37,42.38 38.48,41.49 v38.48,24.22 | v87.24,32.22 87.62,32.6 87.62,36.54 83.81,40.35 83.81,49.87 84.58,50.63 LCD.8 | v12.95,52.03 20.7,44.28 v20.7,28.16 | v33.52,26.25 34.67,25.11 34.67,24.6 D1.17
PE2  (via drill 0.46)
  Top 0.254: v73.91,48.22 74.04,48.35 84.32,48.35 LCD.9 | GLCD.9 5.08,49.62 5.84,48.86 7.49,48.86 8.38,49.75 36.83,49.75 IC1.4 37.84,49.62 38.1,49.62 v40.13,47.59 | v40.25,19.39 51.3,19.39 52.57,20.66 73.15,20.66 74.92,22.44 D0.15
  Bottom 0.254: v73.91,48.22 73.91,26 75.31,24.6 D0.15 | v40.13,47.59 40.13,42.38 39.11,41.36 39.11,25.23 39.75,24.6 D1.15 40.25,22.06 v40.25,19.39
PE3  (via drill 0.46)
  Top 0.254: v34.67,48.98 36.83,48.98 IC1.5 | v33.52,51.02 33.27,50.76 9.01,50.76 v8.5,51.27 | v88.01,67.65 77.46,67.65 76.96,67.14 66.92,67.14 61.34,72.73 v60.96,72.73 | v33.27,74 v59.69,74
  Bottom 0.254: v34.67,48.98 33.52,50.13 v33.52,51.02 33.4,51.4 33.4,53.17 32.63,53.94 32.63,62.19 29.59,65.24 29.59,70.32 v33.27,74 | v8.5,51.27 7.62,50.38 GLCD.10 | v88.01,67.65 88.77,66.89 88.77,48.73 86.86,46.82 LCD.10 | v59.69,74 v60.96,72.73
PE4  (via drill 0.46)
  Top 0.254: v35.43,48.22 36.83,48.22 IC1.6 | v32.51,51.52 30.73,53.3 27.68,53.3 | 27.68,53.3 7.87,53.3 7.49,53.68 3.93,53.68 3.3,53.05 3.3,48.09 4.06,48.09 GLCD.11 | 27.68,53.3 27.68,58.38 27.43,58.64 23.11,58.64 23.11,64.1 23.74,64.73 48,64.73 49.65,63.08 83.05,63.08 84.32,61.81 LCD.4
  Bottom 0.254: v35.43,48.22 32.51,48.22 v32.51,51.52
PE5  (via drill 0.46)
  Top 0.254: v34.92,47.21 36.83,47.21 IC1.7 37.84,47.46 38.1,47.46 v38.6,47.97 | v33.4,44.79 33.14,44.54 10.41,44.54 v10.28,44.41 | v68.32,64.61 68.57,64.35 82.55,64.35 84.2,62.7 87.62,62.7 87.62,60.29 86.86,59.52 LCD.5 | v65.53,67.4 60.96,71.97 56.38,71.97 51.05,66.64 v41.4,66.64
  Bottom 0.254: v34.92,47.21 33.4,45.68 v33.4,44.79 | v10.28,44.41 7.62,47.08 GLCD.12 | v65.53,67.4 v68.32,64.61 | v41.4,66.64 37.59,62.83 37.59,58.38 37.97,58 37.97,48.6 v38.6,47.97
PE6  (via drill 0.46)
  Top 0.254: 28.12,47.78 27.3,48.6 9.77,48.6 7.23,46.06 5.84,46.06 5.08,45.3 GLCD.13 | 28.12,47.78 29.59,46.32 34.41,46.32 34.54,46.44 36.83,46.44 IC1.8 | v88.01,66.51 88.77,67.27 88.77,70.32 v81.53,70.32 | v36.7,63.97 35.94,63.21 v30.47,63.21 | 28.12,47.78 v29.33,48.98
  Bottom 0.254: v88.01,66.51 88.01,58.13 86.86,56.98 LCD.6 | v81.53,70.32 76.32,75.53 36.7,75.53 v36.7,63.97 | v30.47,63.21 29.33,62.06 v29.33,48.98
PE7  (via drill 0.46)
  Top 0.254: 32.63,45.68 28.19,45.68 27.68,45.17 7.62,45.17 GLCD.14 | 32.63,45.68 36.83,45.68 IC1.9 | 32.63,45.68 v32.63,45.55 | v67.69,19.01 67.3,18.63 v33.52,18.63
  Bottom 0.254: v32.63,45.55 32.63,36.79 32.76,36.66 32.76,24.73 32.63,24.6 D1.18 32.63,22.06 32.63,19.52 v33.52,18.63 | v67.69,19.01 67.69,22.06 D0.18
PG0  (via drill 0.46)
  Top 0.254: v54.1,39.84 53.59,39.84 53.34,40.09 IC1.33 | v55.37,34.25 57.15,32.47 58.41,32.47 IC4.29
  Bottom 0.254: v54.1,39.84 54.35,39.59 54.35,35.27 v55.37,34.25
PG1  (via drill 0.46)
  Top 0.254: v54.1,40.98 53.34,40.98 IC1.34 | v55.49,38.95 55.62,38.82 58.41,38.82 IC4.24
  Bottom 0.254: v54.1,40.98 55.49,39.59 v55.49,38.95
PG2  (via drill 0.46)
  Top 0.254: v51.56,48.22 52.32,48.22 IC1.43 | v52.32,54.32 57.02,54.32 57.53,53.81 65.02,53.81 65.78,54.57 IC2.11
  Bottom 0.254: v51.56,48.22 52.32,48.98 v52.32,54.32
PG3  (via drill 0.46)
  Top 0.254: v40,37.17 40,37.94 IC1.18 | v39.87,30.19 37.84,32.22 v35.43,32.22
  Bottom 0.254: v40,37.17 39.87,37.05 v39.87,30.19 | v35.43,32.22 33.9,33.74 33.9,36.66 Q2.1
PG4  (via drill 0.46)
  Top 0.254: v40.89,36.54 40.89,37.94 IC1.19 | v41.02,30.19 43.18,32.35 43.18,35.27 38.48,35.27 36.19,37.55 v35.43,37.55
  Bottom 0.254: v40.89,36.54 41.02,36.41 v41.02,30.19 | v35.43,37.55 33.9,39.08 33.9,39.2 Q2.2
RESET  (via drill 0.46)
  Top 0.254: v76.83,61.56 77.34,62.06 82.67,62.06 83.05,61.68 83.05,60.54 81.15,60.54 IC3.20 | v71.75,68.16 72,67.91 v76.58,67.91 | v42.54,36.54 41.65,36.54 41.65,37.94 IC1.20 | D0.24 52.07,24.22 50.8,25.49 45.84,25.49 v44.57,26.76 44.19,26.63 43.05,25.49 19.55,25.49 v19.3,25.74 | GLCD.17 5.08,40.22 5.84,40.98 18.66,40.98 18.79,40.86 D2.A 20.57,40.86 22.47,40.86 v23.24,41.62 | v69.72,74.77 68.96,75.53 21.97,75.53 19.68,73.24 ISP.5
  Bottom 0.254: DBVR1.2 77.59,51.52 76.83,51.52 v76.83,61.56 76.83,67.65 v76.58,67.91 | v71.75,68.16 71.75,69.43 71.5,69.69 JTAG.6 70.73,70.95 69.72,71.97 v69.72,74.77 | v42.54,36.54 44.57,34.51 v44.57,26.76 | v23.24,41.62 23.24,64.35 20.44,67.14 20.44,70.57 20.06,70.95 20.06,71.59 19.43,72.22 ISP.5 | GLCD.17 4.06,39.2 2.03,37.17 2.03,14.06 7.36,8.73 C5.1 9.14,7.2 11.43,7.2 11.43,7.07 11.55,6.95 13.58,6.95 13.58,7.46 R1.1 14.73,8.73 15.24,9.23 15.24,9.87 RESET.1 15.87,12.79 15.87,21.04 16.89,22.06 D1.24 17.77,24.22 v19.3,25.74
RX  (via drill 0.46)
  Top 0.254: v78.99,57.87 79.75,57.87 IC3.16 | v65.53,63.97 65.15,63.59 52.7,63.59 v52.45,63.84
  Bottom 0.254: v78.99,57.87 78.23,58.64 78.23,60.29 78.35,60.41 78.35,72.73 77.08,74 74.8,74 74.8,68.03 74.42,67.65 74.42,65.49 72.77,63.84 65.53,63.84 v65.53,63.97 | v52.45,63.84 52.07,64.22 52.07,69.18 49.78,71.46 45.33,71.46 45.33,68.41 X1.3
RXD1  (via drill 0.46)
  Top 0.254: v21.46,38.32 36.83,38.32 42.16,43.65 46.98,43.65 46.98,38.95 IC1.27 | v22.35,64.1 24.12,65.88 49.91,65.88 50.16,66.13 62.1,66.13 62.61,66.64 81.02,66.64 v82.55,65.11 | v82.42,58 81.78,57.37 81.15,57.37 IC3.15
  Bottom 0.254: v21.46,38.32 21.58,38.44 21.58,63.34 v22.35,64.1 | v82.55,65.11 83.05,64.61 83.05,60.54 82.42,59.91 v82.42,58
SCL  (via drill 0.46)
  Top 0.254: v54.48,28.16 52.57,30.06 45.59,30.06 45.59,37.94 IC1.25 | v55.37,26.63 79.5,26.63 81.21,28.35 | 81.21,28.35 82.8,29.93 82.8,33.11 84.32,33.11 I2C.2 | 81.21,28.35 v81.4,28.16
  Bottom 0.254: v54.48,28.16 55.37,27.27 v55.37,26.63 | v81.4,28.16 81.4,27.27 R9.1
SDA  (via drill 0.46)
  Top 0.254: v55.11,35.78 46.35,35.78 46.35,37.94 IC1.26 | v56.13,19.9 56.26,19.77 v80.51,19.77 | v80.64,23.96 81.15,24.47 83.81,24.47 83.81,29.55 84.58,30.31 I2C.3
  Bottom 0.254: v55.11,35.78 56.13,34.76 v56.13,19.9 | v80.51,19.77 80.64,19.9 v80.64,23.96 80.64,28.92 81.27,29.55 R10.1
T_EN  (via drill 0.46)
  Top 0.254: v74.54,51.14 v79.37,51.14 | v77.59,60.8 77.34,60.54 73.91,60.54 IC3.1
  Bottom 0.254: v74.54,51.14 74.54,51.02 75.05,50.51 DBVR1.4 | v79.37,51.14 79.37,56.35 77.59,58.13 v77.59,60.8
TCK  (via drill 0.46)
  Top 0.254: IC1.57 44.83,54.45 44.83,57.49 44.95,57.49 ADC.7 46.98,58.51 47.75,57.75 51.94,57.75 54.35,60.16 56.51,60.16 v56.64,60.29 | v75.18,65.11 68.96,65.11 68.7,65.37 63.5,65.37 v63.24,65.11
  Bottom 0.254: v75.18,65.11 75.18,67.65 77.34,69.81 77.34,71.72 JTAG.1 | v63.24,65.11 61.08,67.27 61.08,70.95 58.03,74 54.73,74 54.73,63.46 56.64,61.56 v56.64,60.29
TDI  (via drill 0.46)
  Top 0.254: v46.98,55.21 46.98,54.45 IC1.54 | ADC.10 48.26,61.05 47.49,60.29 45.72,60.29 v45.21,59.78 45.08,59.4 45.08,58.51 44.32,57.75 37.21,57.75 v36.19,56.73 | v33.52,17.49 29.08,13.04 S1.9 | v64,72.48 65.4,72.48 JTAG.9 | v64,64.35 53.08,64.35 52.83,64.61 v49.65,64.61
  Bottom 0.254: v46.98,55.21 45.21,56.98 v45.21,59.78 | v33.52,17.49 36.19,20.15 v36.19,56.73 | v64,64.35 v64,72.48 | v49.65,64.61 49.27,64.22 49.27,62.06 ADC.10
TDO  (via drill 0.46)
  Top 0.254: v46.98,56.35 46.22,56.35 46.22,54.45 IC1.55 | v72.51,65.88 62.61,65.88 62.1,65.37 v50.54,65.37
  Bottom 0.254: v46.98,56.35 48.51,57.87 48.51,58.25 ADC.9 48.51,59.52 48.51,59.78 47.75,60.54 47.75,65.37 v50.54,65.37 | v72.51,65.88 72.51,71.46 73.27,72.22 JTAG.3
TMS  (via drill 0.46)
  Top 0.254: v46.22,57.11 45.59,57.11 45.59,54.45 IC1.56 | v47.49,69.18 49.78,69.18 53.08,72.48 59.3,72.48 60.83,74 69.72,74 70.48,73.24 JTAG.5
  Bottom 0.254: v46.22,57.11 47.49,58.38 47.49,60.03 46.73,60.8 ADC.8 46.73,62.06 46.73,68.41 v47.49,69.18
TX  (via drill 0.46)
  Top 0.254: v75.31,58.51 75.43,58.64 79.75,58.64 IC3.17 | v46.48,74.77 v64.77,74.77
  Bottom 0.254: v75.31,58.51 74.29,59.52 74.29,62.57 73.66,63.21 64.77,63.21 v64.77,74.77 | v46.48,74.77 42.54,70.83 42.54,68.41 X1.2
TXD1  (via drill 0.46)
  Top 0.254: v48,36.54 48,37.94 IC1.28 | v48.13,27.52 48.26,27.39 v57.65,27.39 | v62.35,40.48 63.24,41.36 v65.02,41.36 | v66.8,48.48 67.05,48.22 69.84,48.22 v72.77,51.14 | v75.31,57.37 75.56,57.11 78.48,57.11 79.5,56.1 79.75,56.1 IC3.13
  Bottom 0.254: v48,36.54 48.13,36.41 v48.13,27.52 | v57.65,27.39 60.32,30.06 60.32,38.44 v62.35,40.48 | v65.02,41.36 66.8,43.14 v66.8,48.48 | v72.77,51.14 74.29,52.67 74.29,56.35 v75.31,57.37
VCC  (via drill 0.46)
  Top 0.381: V1.1 D0.10 69.84,16.6 68.96,17.49 54.22,17.49 53.34,16.6 D0.3 D1.10 | v82.8,23.71 84.32,23.71 V2.1 | IC4.30 60.19,30.7 60.7,30.7 60.7,29.04 60.57,28.92 60.45,28.92 60.19,28.66 IC4.32 60.19,28.16 60.32,28.03 v60.96,28.03 | v13.08,14.19 13.71,14.82 16.5,14.82 D1.3 | v22.22,5.42 22.98,5.42 S1.2 | GLCD.19 5.08,36.92 5.96,36.03 18.54,36.03 18.79,36.28 D2.C 20.57,36.92 v22.22,36.92 | D1.22 D1.21 | v22.35,47.08 23.11,47.08 C3.+ | v64.51,60.54 65.78,60.54 IC2.20 67.18,60.67 67.69,61.18 74.92,61.18 v75.05,61.3 | v83.56,59.91 81.15,59.91 IC3.19 | v84.32,71.59 75.18,71.59 74.29,70.7 JTAG.4 73.02,70.7 72.13,71.59 70.1,71.59 69.21,72.48 JTAG.7 67.94,72.48 67.05,71.59 63.62,71.59 v61.97,73.24 | v76.07,65.75 75.81,66 73.78,66 v73.66,65.88 | GLCD.2 7.36,60.8 7.36,68.8 12.44,68.8 12.7,69.05 22.6,69.05 23.49,69.94 ISP.2 | 42.29,39.71 42.29,38.95 IC1.21 | 42.29,39.71 v39.87,39.71 | v49.02,52.67 48.64,52.67 48.64,53.43 IC1.52 | v45.46,42.89 42.29,39.71 | ADC.11 51.05,59.52 50.16,59.52 50.16,61.81 49.27,62.7 40.25,62.7 39.37,61.81 ADC.2 33.02,61.43 L1.1 31.74,62.19 27.17,62.19 REG1.P$3 24.12,63.21 v24.12,63.97 | v24.76,7.71 36.7,7.71 36.83,7.84 CONT.E
  Bottom 0.381: 83.81,37.17 84.45,36.54 I2C.1 | 83.81,37.17 82.55,38.44 R11.2 | 83.81,37.17 83.69,37.05 83.69,33.49 82.55,32.35 R10.2 82.55,31.58 83.18,30.95 83.18,25.62 82.55,25.62 R9.2 82.55,24.47 82.8,24.22 v82.8,23.71 | V2.1 86.86,22.7 87.75,21.81 87.75,17.23 86.86,16.34 V1.1 | R8.2 33.78,4.92 36.83,7.96 CONT.E 37.21,8.73 37.21,12.41 35.17,14.44 D1.10 | R5.2 49.91,8.73 49.91,11.9 52.45,14.44 D0.3 53.34,16.6 57.78,16.6 57.78,17.23 58.16,17.61 C14.1 58.16,19.14 58.03,19.27 58.03,22.06 D0.22 58.03,24.6 60.19,26.76 60.19,28.28 60.45,28.54 | 60.45,28.54 60.7,28.79 C15.1 | 60.45,28.54 v60.96,28.03 | v13.08,14.19 13.08,8.73 R1.2 | C13.1 24.38,20.41 24.51,20.54 24.51,22.06 D1.21 | 22.35,36.92 22.35,24.6 D1.22 21.97,22.06 21.97,20.79 17.77,16.6 D1.3 17.39,14.44 17.39,10.25 v22.22,5.42 22.6,5.55 v24.76,7.71 | 22.35,36.92 22.35,40.73 | 22.35,40.73 v22.35,47.08 | 22.35,36.92 v22.22,36.92 | DBVR1.5 75.56,52.41 75.56,54.19 C10.1 76.19,55.97 76.19,60.16 v75.05,61.3 75.18,61.68 76.07,62.57 v76.07,65.75 | v64.51,60.54 63.75,59.78 C16.1 | v83.56,59.91 83.69,60.03 83.69,64.99 84.58,65.88 LCD.2 86.86,67.14 86.86,67.78 87.75,68.67 87.75,69.43 85.72,71.46 85.72,71.59 v84.32,71.59 | JTAG.4 v73.66,65.88 | v39.87,39.71 40.38,40.22 C17.1 | 54.1,63.08 54.61,62.57 54.61,61.56 R6.2 | 54.1,63.08 52.95,63.08 52.95,62.7 52.7,62.45 52.7,60.41 51.81,59.52 ADC.11 51.05,58.25 51.05,54.95 49.14,53.05 v49.02,52.67 48.51,52.16 C18.1 46.98,50.38 46.98,44.41 v45.46,42.89 | ISP.2 v24.12,63.97 24.12,40.73 22.35,40.73 | v61.97,73.24 61.72,73.24 60.07,74.89 54.1,74.89 54.1,63.08
VEE
  Top 0.254: 22.66,9.55 23.74,8.47 28.44,8.47 28.57,8.34 36.19,8.34 36.95,9.11 41.14,9.11 41.91,8.34 CONT.A | 22.66,9.55 21.46,10.76 S1.12 | GLCD.18 6.34,39.46 5.33,38.44 3.93,38.44 2.03,36.54 2.03,9.49 22.6,9.49 22.66,9.55
VRGB  (via drill 0.46)
  Top 0.254: v26.03,14.44 25.39,14.44 24,13.04 S1.11
  Bottom 0.254: RB.2 29.08,32.85 29.08,31.58 RG.2 29.08,30.31 29.08,29.04 RR.2 28.44,27.77 26.28,25.62 26.28,14.69 v26.03,14.44
XTAL1  (via drill 0.46)
  Top 0.254: IC1.24 44.83,37.94 44.83,30.06 45.33,29.55 49.78,29.55 50.54,28.79 C1.1 51.56,28.79 51.68,28.79 v52.19,29.3 | v52.19,30.82 51.68,30.82 51.68,32.73 Q1.1
  Bottom 0.254: v52.19,29.3 v52.19,30.82
XTAL2  (via drill 0.46)
  Top 0.254: v36.95,30.44 38.6,28.79 C2.1 39.62,28.03 40.13,27.52 v45.33,27.52 | v36.95,32.98 37.84,32.98 Q1.2 | v44.06,36.54 44.06,37.94 IC1.23
  Bottom 0.254: v36.95,30.44 v36.95,32.98 | v44.06,36.54 45.33,35.27 v45.33,27.52

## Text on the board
tDocu: ISP | JTAG | 1 | + | + | 1 | 7 | G | 1 | G | 0 | 6 | + | 0 | 1 | PE | 0 | 6 | 7 | 16 | 6 | 7 | 20 | 0 | + | D5 | D6 | + | D7 | 6 | 7 | G | 4 | + | G | + | 7 | C | L | N | K | B | M | G | ATMEGA128 DEV BOARD | 2005.08.14 WILLIAM S. DUBEL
